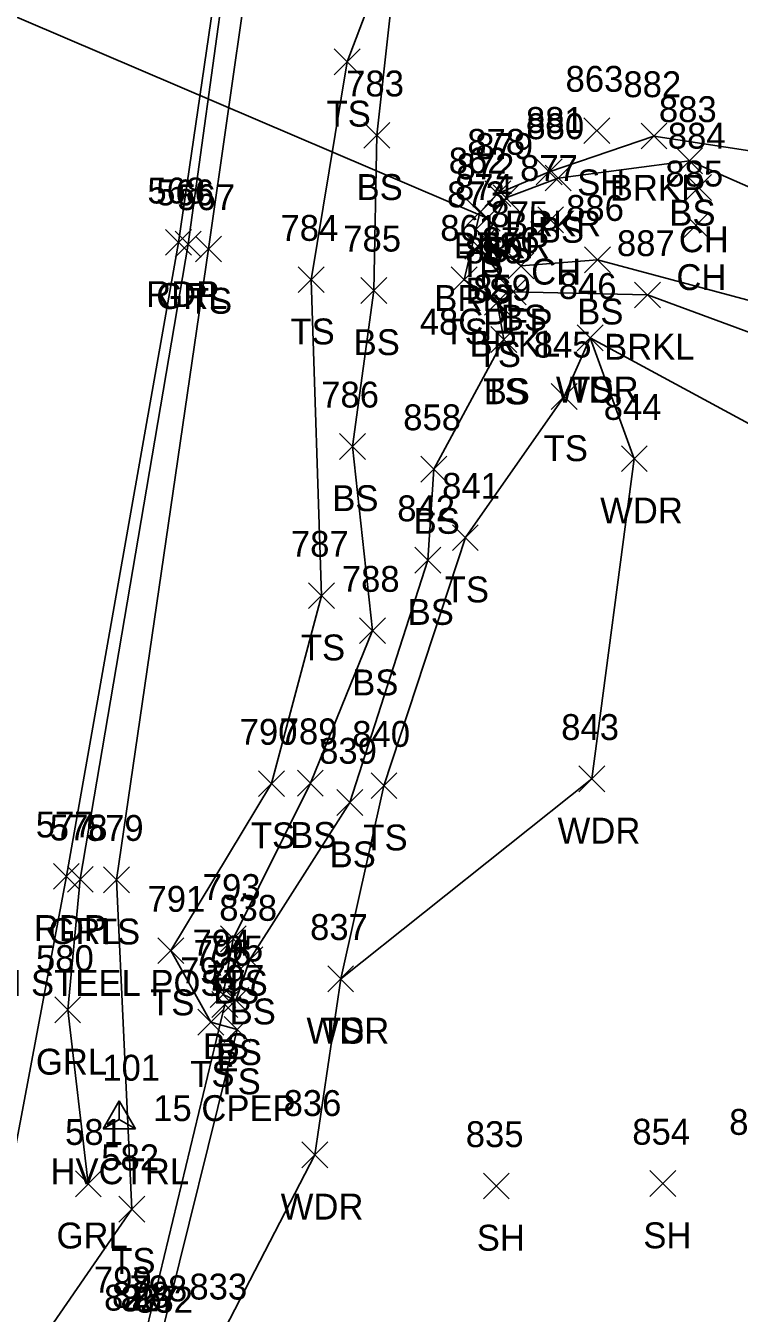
# Model space of a CAD drawing. Extents: x 1638705 to 1644019, y 630225 to 637423.
# Drawn here: x 1643884.4 to 1643939.5, y 636967.4 to 637066.8 of the extents above; entities that cross this region are included whole.
import ezdxf

# ---------------------------------------------------------------- set-up
doc = ezdxf.new("R2010")
doc.units = 0
for name, color, linetype in [('C_A', 7, 'Continuous'), ('C_I', 7, 'Continuous'), ('CPSM', 7, 'Continuous'), ('D_A', 7, 'Continuous'), ('D_C', 7, 'Continuous'), ('D_I', 7, 'Continuous'), ('D_TIC', 7, 'Continuous'), ('DCP', 7, 'Continuous'), ('L_A', 7, 'Continuous'), ('L_I', 7, 'Continuous'), ('L_TIC', 7, 'Continuous'), ('LAWA', 7, 'Continuous'), ('LAWE', 7, 'Continuous'), ('LELB', 7, 'Continuous'), ('P_A', 7, 'Continuous'), ('P_I', 7, 'Continuous'), ('P_TIC', 7, 'Continuous'), ('PET', 7, 'Continuous'), ('R_A', 7, 'Continuous'), ('R_C', 7, 'Continuous'), ('R_I', 7, 'Continuous'), ('R_TIC', 7, 'Continuous'), ('RGR', 7, 'Continuous')]:
    doc.layers.add(name, color=color, linetype=linetype)

msp = doc.modelspace()

# ---------------------------------------------------------------- linework, layer by layer
at = {"layer": 'CPSM'}
for p, q in [((1643890.37, 636981.613), (1643891.62, 636983.778)), ((1643892.87, 636981.613), (1643891.62, 636983.778)), ((1643891.62, 636982.334), (1643891.62, 636983.778)), ((1643890.37, 636981.613), (1643891.62, 636982.334)), ((1643890.37, 636981.613), (1643892.87, 636981.613)), ((1643891.62, 636982.334), (1643891.62, 636982.334)), ((1643891.62, 636982.334), (1643892.87, 636981.613))]:
    msp.add_line(p, q, dxfattribs=at)
at = {"layer": 'D_TIC'}
for points in [[(1643919.023, 637050.962), (1643921.023, 637052.962)], [(1643921.023, 637050.962), (1643919.023, 637052.962)], [(1643898.776, 636990.211), (1643900.776, 636992.211)], [(1643900.776, 636990.211), (1643898.776, 636992.211)]]:
    msp.add_lwpolyline(points, dxfattribs=at)
at = {"layer": 'DCP'}
for points in [[(1643845.619, 637083.784), (1643920.023, 637051.962)], [(1643899.776, 636991.211), (1643893.426, 636964.792)]]:
    msp.add_lwpolyline(points, dxfattribs=at)
at = {"layer": 'L_TIC'}
for points in [[(1643908.215, 637063.03), (1643910.215, 637065.03)], [(1643910.215, 637063.03), (1643908.215, 637065.03)], [(1643910.501, 637057.36), (1643912.501, 637059.36)], [(1643912.501, 637057.36), (1643910.501, 637059.36)], [(1643927.486, 637057.719), (1643929.486, 637059.719)], [(1643929.486, 637057.719), (1643927.486, 637059.719)], [(1643931.903, 637057.304), (1643933.903, 637059.304)], [(1643933.903, 637057.304), (1643931.903, 637059.304)], [(1643934.645, 637055.378), (1643936.645, 637057.378)], [(1643936.645, 637055.378), (1643934.645, 637057.378)], [(1643923.807, 637054.542), (1643925.807, 637056.542)], [(1643925.807, 637054.542), (1643923.807, 637056.542)], [(1643924.501, 637054.058), (1643926.501, 637056.058)], [(1643926.501, 637054.058), (1643924.501, 637056.058)], [(1643935.333, 637053.328), (1643937.333, 637055.328)], [(1643937.333, 637053.328), (1643935.333, 637055.328)], [(1643919.854, 637052.851), (1643921.854, 637054.851)], [(1643921.854, 637052.851), (1643919.854, 637054.851)], [(1643919.854, 637052.851), (1643921.854, 637054.851)], [(1643921.854, 637052.851), (1643919.854, 637054.851)], [(1643920.475, 637052.525), (1643922.475, 637054.525)], [(1643922.475, 637052.525), (1643920.475, 637054.525)], [(1643918.467, 637051.406), (1643920.467, 637053.406)], [(1643920.467, 637051.406), (1643918.467, 637053.406)], [(1643923.928, 637050.828), (1643925.928, 637052.828)], [(1643925.928, 637050.828), (1643923.928, 637052.828)], [(1643935.145, 637050.403), (1643937.145, 637052.403)], [(1643937.145, 637050.403), (1643935.145, 637052.403)], [(1643918.905, 637049.362), (1643920.905, 637051.362)], [(1643920.905, 637049.362), (1643918.905, 637051.362)], [(1643918.905, 637049.362), (1643920.905, 637051.362)], [(1643920.905, 637049.362), (1643918.905, 637051.362)], [(1643897.51, 637048.576), (1643899.51, 637050.576)], [(1643899.51, 637048.576), (1643897.51, 637050.576)], [(1643918.294, 637048.795), (1643920.294, 637050.795)], [(1643920.294, 637048.795), (1643918.294, 637050.795)], [(1643921.637, 637047.27), (1643923.637, 637049.27)], [(1643923.637, 637047.27), (1643921.637, 637049.27)], [(1643927.537, 637047.745), (1643929.537, 637049.745)], [(1643929.537, 637047.745), (1643927.537, 637049.745)], [(1643905.43, 637046.206), (1643907.43, 637048.206)], [(1643907.43, 637046.206), (1643905.43, 637048.206)], [(1643917.245, 637046.205), (1643919.245, 637048.205)], [(1643919.245, 637046.205), (1643917.245, 637048.205)], [(1643910.276, 637045.378), (1643912.276, 637047.378)], [(1643912.276, 637045.378), (1643910.276, 637047.378)], [(1643921.024, 637045.261), (1643923.024, 637047.261)], [(1643923.024, 637045.261), (1643921.024, 637047.261)], [(1643931.404, 637045.025), (1643933.404, 637047.025)], [(1643933.404, 637045.025), (1643931.404, 637047.025)], [(1643919.807, 637044.463), (1643921.807, 637046.463)], [(1643921.807, 637044.463), (1643919.807, 637046.463)], [(1643920.314, 637041.585), (1643922.314, 637043.585)], [(1643922.314, 637041.585), (1643920.314, 637043.585)], [(1643920.314, 637041.585), (1643922.314, 637043.585)], [(1643922.314, 637041.585), (1643920.314, 637043.585)], [(1643926.967, 637041.714), (1643928.967, 637043.714)], [(1643928.967, 637041.714), (1643926.967, 637043.714)], [(1643926.967, 637041.714), (1643928.967, 637043.714)], [(1643928.967, 637041.714), (1643926.967, 637043.714)], [(1643924.978, 637037.189), (1643926.978, 637039.189)], [(1643926.978, 637037.189), (1643924.978, 637039.189)], [(1643908.627, 637033.328), (1643910.627, 637035.328)], [(1643910.627, 637033.328), (1643908.627, 637035.328)], [(1643930.383, 637032.377), (1643932.383, 637034.377)], [(1643932.383, 637032.377), (1643930.383, 637034.377)], [(1643914.906, 637031.575), (1643916.906, 637033.575)], [(1643916.906, 637031.575), (1643914.906, 637033.575)], [(1643917.342, 637026.278), (1643919.342, 637028.278)], [(1643919.342, 637026.278), (1643917.342, 637028.278)], [(1643914.445, 637024.542), (1643916.445, 637026.542)], [(1643916.445, 637024.542), (1643914.445, 637026.542)], [(1643906.234, 637021.797), (1643908.234, 637023.797)], [(1643908.234, 637021.797), (1643906.234, 637023.797)], [(1643910.166, 637019.094), (1643912.166, 637021.094)], [(1643912.166, 637019.094), (1643910.166, 637021.094)], [(1643902.367, 637007.279), (1643904.367, 637009.279)], [(1643904.367, 637007.279), (1643902.367, 637009.279)], [(1643905.375, 637007.314), (1643907.375, 637009.314)], [(1643907.375, 637007.314), (1643905.375, 637009.314)], [(1643927.102, 637007.646), (1643929.102, 637009.646)], [(1643929.102, 637007.646), (1643927.102, 637009.646)], [(1643911.058, 637007.117), (1643913.058, 637009.117)], [(1643913.058, 637007.117), (1643911.058, 637009.117)], [(1643908.422, 637005.815), (1643910.422, 637007.815)], [(1643910.422, 637005.815), (1643908.422, 637007.815)], [(1643890.408, 636999.854), (1643892.408, 637001.854)], [(1643892.408, 636999.854), (1643890.408, 637001.854)], [(1643899.427, 636995.286), (1643901.427, 636997.286)], [(1643901.427, 636995.286), (1643899.427, 636997.286)], [(1643894.601, 636994.378), (1643896.601, 636996.378)], [(1643896.601, 636994.378), (1643894.601, 636996.378)], [(1643900.703, 636993.68), (1643902.703, 636995.68)], [(1643902.703, 636993.68), (1643900.703, 636995.68)], [(1643907.716, 636992.198), (1643909.716, 636994.198)], [(1643909.716, 636992.198), (1643907.716, 636994.198)], [(1643907.716, 636992.198), (1643909.716, 636994.198)], [(1643909.716, 636992.198), (1643907.716, 636994.198)], [(1643898.633, 636990.996), (1643900.633, 636992.996)], [(1643900.633, 636990.996), (1643898.633, 636992.996)], [(1643899.629, 636990.537), (1643901.629, 636992.537)], [(1643901.629, 636990.537), (1643899.629, 636992.537)], [(1643897.693, 636988.856), (1643899.693, 636990.856)], [(1643899.693, 636988.856), (1643897.693, 636990.856)], [(1643899.72, 636988.28), (1643901.72, 636990.28)], [(1643901.72, 636988.28), (1643899.72, 636990.28)], [(1643905.725, 636978.603), (1643907.725, 636980.603)], [(1643907.725, 636978.603), (1643905.725, 636980.603)], [(1643932.591, 636976.387), (1643934.591, 636978.387)], [(1643934.591, 636976.387), (1643932.591, 636978.387)], [(1643919.735, 636976.2), (1643921.735, 636978.2)], [(1643921.735, 636976.2), (1643919.735, 636978.2)], [(1643891.594, 636974.409), (1643893.594, 636976.409)], [(1643893.594, 636974.409), (1643891.594, 636976.409)]]:
    msp.add_lwpolyline(points, dxfattribs=at)
at = {"layer": 'LAWA'}
msp.add_lwpolyline([(1643866.424, 636846.235), (1643870.334, 636868.741), (1643881.968, 636887.155), (1643890.891, 636910.041), (1643901.918, 636941.196), (1643899.231, 636950.312), (1643899.398, 636965.426), (1643906.725, 636979.603), (1643908.716, 636993.198), (1643928.102, 637008.646), (1643931.383, 637033.377), (1643927.967, 637042.714)], dxfattribs=at)
at = {"layer": 'LAWE'}
for points in [[(1643920.854, 637053.851), (1643924.807, 637055.542), (1643932.903, 637058.304), (1643947.715, 637056.023), (1643968.127, 637052.572), (1643983.362, 637045.543), (1643983.839, 637027.524), (1643981.944, 637013.462), (1643978.002, 636996.651), (1643988.429, 636970.063), (1644005.748, 636951.026)], [(1643919.294, 637049.795), (1643922.024, 637046.261), (1643932.404, 637046.025), (1643943.492, 637041.947), (1643951.847, 637033.709), (1643954.828, 637020.437), (1643953.404, 636994.74), (1643959.423, 636977.354), (1643969.521, 636961.152), (1643976.439, 636955.025), (1643988.351, 636934.413)]]:
    msp.add_lwpolyline(points, dxfattribs=at)
at = {"layer": 'LELB'}
for points in [[(1643920.864, 637305.094), (1643921.579, 637262.309), (1643919.171, 637218.5), (1643918.101, 637180.784), (1643916.282, 637160.367), (1643916.867, 637121.441), (1643917.546, 637101.695), (1643908.97, 637083.26), (1643913.322, 637074.892), (1643911.501, 637058.36), (1643911.276, 637046.378), (1643909.627, 637034.328), (1643911.166, 637020.094), (1643906.375, 637008.314), (1643900.427, 636996.286), (1643899.633, 636991.996), (1643900.629, 636991.537), (1643901.703, 636994.68), (1643909.422, 637006.815), (1643915.445, 637025.542), (1643915.906, 637032.575), (1643921.314, 637042.585)], [(1643917.287, 637304.481), (1643919.245, 637262.47), (1643916.887, 637218.548), (1643914.082, 637180.953), (1643910.304, 637135.874), (1643913.16, 637114.459), (1643911.21, 637098.669), (1643904.371, 637090.608), (1643898.51, 637049.576), (1643891.408, 637000.854), (1643892.594, 636975.409), (1643882.007, 636960.09), (1643871.052, 636914.879), (1643861.764, 636881.64), (1643855.169, 636855.929)], [(1643913.322, 637074.892), (1643909.215, 637064.03), (1643906.43, 637047.206), (1643907.234, 637022.797), (1643903.367, 637008.279), (1643895.601, 636995.378), (1643898.693, 636989.856), (1643900.72, 636989.28), (1643894.769, 636965.285), (1643892.036, 636965.966), (1643886.161, 636959.847), (1643884.56, 636948.28), (1643890.237, 636948.659), (1643892.561, 636955.567), (1643895.216, 636964.409)], [(1643919.905, 637050.362), (1643921.475, 637053.525), (1643925.501, 637055.058), (1643935.645, 637056.378), (1643945.354, 637052.121), (1643966.131, 637048.505), (1643981.61, 637044.262), (1643982.709, 637028.601), (1643978.04, 637012.057), (1643976.281, 636996.57), (1643984.924, 636970.452), (1643996.538, 636958.915), (1644004.829, 636948.618)], [(1643921.314, 637042.585), (1643920.807, 637045.463), (1643918.245, 637047.205), (1643919.467, 637052.406), (1643920.854, 637053.851)], [(1643919.905, 637050.362), (1643922.637, 637048.27), (1643928.537, 637048.745), (1643944.782, 637044.377), (1643954.955, 637036.722), (1643955.986, 637020.996), (1643955.788, 636997.511), (1643964.067, 636979.153), (1643972.552, 636962.501), (1643978.917, 636953.806), (1643985.678, 636940.472)], [(1643908.716, 636993.198), (1643912.058, 637008.117), (1643918.342, 637027.278), (1643925.978, 637038.189), (1643927.967, 637042.714), (1643941.817, 637035.217), (1643949.251, 637027.496), (1643949.31, 637011.852), (1643946.753, 636999.207), (1643949.874, 636992.362), (1643957.892, 636976.474), (1643964.831, 636964.871), (1643973.423, 636952.162), (1643973.829, 636947.917), (1643979.82, 636937.594), (1643993.779, 636923.912)]]:
    msp.add_lwpolyline(points, dxfattribs=at)
at = {"layer": 'P_TIC'}
for points in [[(1643895.203, 637049.089), (1643897.203, 637051.089)], [(1643897.203, 637049.089), (1643895.203, 637051.089)], [(1643886.538, 637000.119), (1643888.538, 637002.119)], [(1643888.538, 637000.119), (1643886.538, 637002.119)]]:
    msp.add_lwpolyline(points, dxfattribs=at)
at = {"layer": 'PET'}
msp.add_lwpolyline([(1643915.423, 637304.493), (1643914.603, 637262.423), (1643913.476, 637219.012), (1643911.31, 637181.13), (1643907.879, 637136.037), (1643902.195, 637091.185), (1643896.203, 637050.089), (1643887.538, 637001.119), (1643879.881, 636960.462), (1643869.1, 636915.332), (1643860.496, 636882.079), (1643852.885, 636856.282)], dxfattribs=at)
at = {"layer": 'R_TIC'}
for points in [[(1643895.935, 637048.945), (1643897.935, 637050.945)], [(1643897.935, 637048.945), (1643895.935, 637050.945)], [(1643887.616, 636999.886), (1643889.616, 637001.886)], [(1643889.616, 636999.886), (1643887.616, 637001.886)], [(1643886.642, 636989.798), (1643888.642, 636991.798)], [(1643888.642, 636989.798), (1643886.642, 636991.798)], [(1643888.233, 636976.37), (1643890.233, 636978.37)], [(1643890.233, 636976.37), (1643888.233, 636978.37)]]:
    msp.add_lwpolyline(points, dxfattribs=at)
at = {"layer": 'RGR'}
msp.add_lwpolyline([(1643912.007, 637114.651), (1643906.946, 637106.495), (1643902.657, 637091.376), (1643896.935, 637049.945), (1643888.616, 637000.886), (1643887.642, 636990.798), (1643889.233, 636977.37)], dxfattribs=at)

# ---------------------------------------------------------------- texts
at = {"layer": 'C_A'}
msp.add_text('HVCTRL', height=2, dxfattribs=at).set_placement((1643886.313, 636977.334))
at = {"layer": 'C_I'}
msp.add_text('101', height=2, dxfattribs=at).set_placement((1643890.313, 636985.334))
at = {"layer": 'D_A'}
for p in [(1643919.401, 637046.962), (1643899.154, 636986.211)]:
    msp.add_text('P', height=2, dxfattribs=at).set_placement(p)
at = {"layer": 'D_C'}
for s, p in [('48CPEP', (1643914.818, 637042.962)), ('15 CPEP', (1643894.24, 636982.211))]:
    msp.add_text(s, height=2, dxfattribs=at).set_placement(p)
at = {"layer": 'D_I'}
for s, p in [('872', (1643917.66, 637054.962)), ('796', (1643897.358, 636994.211)), ('828', (1643891.064, 636967.792))]:
    msp.add_text(s, height=2, dxfattribs=at).set_placement(p)
at = {"layer": 'L_A'}
for s, p in [('TS', (1643907.624, 637059.03)), ('BS', (1643909.942, 637053.36)), ('SH', (1643926.974, 637053.719)), ('BRKR', (1643929.493, 637053.304)), ('BS', (1643934.086, 637051.378)), ('BRKR', (1643921.398, 637050.542)), ('BS', (1643923.941, 637050.058)), ('CH', (1643934.821, 637049.328)), ('BRKR', (1643917.445, 637048.851)), ('TS', (1643919.264, 637048.851)), ('BS', (1643919.916, 637048.525)), ('TS', (1643917.877, 637047.406)), ('CH', (1643923.416, 637046.828)), ('CH', (1643934.633, 637046.403)), ('BS', (1643918.346, 637045.362)), ('BS', (1643918.346, 637045.362)), ('TS', (1643896.919, 637044.576)), ('BRKL', (1643915.94, 637044.795)), ('BS', (1643921.078, 637043.27)), ('BS', (1643926.978, 637043.745)), ('TS', (1643904.839, 637042.206)), ('TS', (1643916.654, 637042.205)), ('BS', (1643909.717, 637041.378)), ('BRKL', (1643918.669, 637041.261)), ('BRKL', (1643929.049, 637041.025)), ('TS', (1643919.216, 637040.463)), ('TS', (1643919.723, 637037.585)), ('BS', (1643919.755, 637037.585)), ('WDR', (1643925.33, 637037.714)), ('TS', (1643926.377, 637037.714)), ('TS', (1643924.388, 637033.189)), ('BS', (1643908.068, 637029.328)), ('WDR', (1643928.745, 637028.377)), ('BS', (1643914.347, 637027.575)), ('TS', (1643916.751, 637022.278)), ('BS', (1643913.886, 637020.542)), ('TS', (1643905.643, 637017.797)), ('BS', (1643909.607, 637015.094)), ('TS', (1643901.777, 637003.279)), ('BS', (1643904.816, 637003.314)), ('WDR', (1643925.465, 637003.646)), ('TS', (1643910.467, 637003.117)), ('BS', (1643907.863, 637001.815)), ('TS', (1643889.817, 636995.854)), ('BS', (1643898.868, 636991.286)), ('TS', (1643894.01, 636990.378)), ('BS', (1643900.144, 636989.68)), ('WDR', (1643906.078, 636988.198)), ('TS', (1643907.125, 636988.198)), ('BS', (1643898.074, 636986.996)), ('BS', (1643899.07, 636986.537)), ('TS', (1643897.103, 636984.856)), ('TS', (1643899.13, 636984.28)), ('WDR', (1643904.087, 636974.603)), ('SH', (1643932.079, 636972.387)), ('SH', (1643919.223, 636972.2)), ('TS', (1643891.003, 636970.409))]:
    msp.add_text(s, height=2, dxfattribs=at).set_placement(p)
at = {"layer": 'L_I'}
for s, p in [('783', (1643909.139, 637061.36)), ('863', (1643926.076, 637061.719)), ('882', (1643930.541, 637061.304)), ('883', (1643933.283, 637059.378)), ('881', (1643923.012, 637058.542)), ('880', (1643923.052, 637058.058)), ('884', (1643933.971, 637057.328)), ('878', (1643918.492, 637056.851)), ('878', (1643918.492, 637056.851)), ('879', (1643919.105, 637056.525)), ('862', (1643917.058, 637055.406)), ('877', (1643922.566, 637054.828)), ('885', (1643933.782, 637054.403)), ('874', (1643917.542, 637053.362)), ('874', (1643917.542, 637053.362)), ('567', (1643896.1, 637052.576)), ('873', (1643916.932, 637052.795)), ('875', (1643920.275, 637051.27)), ('886', (1643926.12, 637051.745)), ('784', (1643904.068, 637050.206)), ('861', (1643916.403, 637050.205)), ('785', (1643908.914, 637049.378)), ('876', (1643919.606, 637049.261)), ('887', (1643930.041, 637049.025)), ('860', (1643918.311, 637048.463)), ('859', (1643918.944, 637045.585)), ('859', (1643918.944, 637045.585)), ('846', (1643925.55, 637045.714)), ('846', (1643925.55, 637045.714)), ('845', (1643923.616, 637041.189)), ('786', (1643907.21, 637037.328)), ('844', (1643929.021, 637036.377)), ('858', (1643913.544, 637035.575)), ('841', (1643916.547, 637030.278)), ('842', (1643913.083, 637028.542)), ('787', (1643904.872, 637025.797)), ('788', (1643908.804, 637023.094)), ('790', (1643900.918, 637011.279)), ('789', (1643904.005, 637011.314)), ('843', (1643925.74, 637011.646)), ('840', (1643909.609, 637011.117)), ('839', (1643907.052, 637009.815)), ('579', (1643889.038, 637003.854)), ('793', (1643898.065, 636999.286)), ('791', (1643893.805, 636998.378)), ('838', (1643899.341, 636997.68)), ('837', (1643906.353, 636996.198)), ('837', (1643906.353, 636996.198)), ('794', (1643897.271, 636994.996)), ('795', (1643898.267, 636994.537)), ('792', (1643896.331, 636992.856)), ('797', (1643898.358, 636992.28)), ('836', (1643904.307, 636982.603)), ('854', (1643931.228, 636980.387)), ('853', (1643938.71, 636981.147)), ('835', (1643918.373, 636980.2)), ('582', (1643890.231, 636978.409)), ('799', (1643889.666, 636968.966)), ('833', (1643897.035, 636968.426)), ('833', (1643897.035, 636968.426)), ('826', (1643890.446, 636967.573)), ('827', (1643891.723, 636967.51)), ('798', (1643892.407, 636968.285)), ('832', (1643892.854, 636967.409))]:
    msp.add_text(s, height=2, dxfattribs=at).set_placement(p)
at = {"layer": 'P_A'}
for p in [(1643893.691, 637045.089), (1643885.026, 636996.119)]:
    msp.add_text('RDP', height=2, dxfattribs=at).set_placement(p)
at = {"layer": 'P_I'}
for s, p in [('568', (1643893.793, 637053.089)), ('577', (1643885.176, 637004.119))]:
    msp.add_text(s, height=2, dxfattribs=at).set_placement(p)
at = {"layer": 'R_A'}
for p in [(1643894.478, 637044.945), (1643886.159, 636995.886), (1643885.185, 636985.798), (1643886.776, 636972.37)]:
    msp.add_text('GRL', height=2, dxfattribs=at).set_placement(p)
at = {"layer": 'R_C'}
msp.add_text('SGR WITH STEEL POSTS', height=2, dxfattribs=at).set_placement((1643870.694, 636991.886))
at = {"layer": 'R_I'}
for s, p in [('566', (1643894.47, 637052.945)), ('578', (1643886.253, 637003.886)), ('580', (1643885.193, 636993.798)), ('581', (1643887.438, 636980.37))]:
    msp.add_text(s, height=2, dxfattribs=at).set_placement(p)

doc.saveas('drawing.dxf')
